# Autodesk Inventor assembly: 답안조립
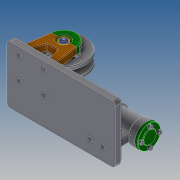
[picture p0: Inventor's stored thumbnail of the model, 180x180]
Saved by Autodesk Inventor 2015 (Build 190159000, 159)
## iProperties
Created: 2018-01
Part Number: 답안조립
Document SubType Name: Assembly
Designer: SCD-A03
Author: SCD-A03
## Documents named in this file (19)
- C:\Users\SCD-A03\Desktop\380108V1008\답안조립.iam
- C:\Users\SCD-A03\Desktop\380108V1008\플레이트.ipt
- C:\Users\SCD-A03\Desktop\380108V1008\3mm 와셔.ipt
- C:\Users\SCD-A03\Desktop\380108V1008\V-벨트풀리.ipt
- C:\Users\SCD-A03\Desktop\380108V1008\둥근머리볼트 M3x12.ipt
- C:\Users\SCD-A03\Desktop\380108V1008\베어링 8x22x7.ipt
- C:\Users\SCD-A03\Desktop\380108V1008\베어링커버-A.ipt
- C:\Users\SCD-A03\Desktop\380108V1008\볼트 M3x8.ipt
- C:\Users\SCD-A03\Desktop\380108V1008\볼트 M3x12.ipt
- C:\Users\SCD-A03\Desktop\380108V1008\스페이서.ipt
- C:\Users\SCD-A03\Desktop\380108V1008\지지대-A.ipt
- C:\Users\SCD-A03\Desktop\380108V1008\커넥팅로드-A.ipt
- C:\Users\SCD-A03\Desktop\380108V1008\커넥팅로드-B.ipt
- C:\Users\SCD-A03\Desktop\380108V1008\크랭크축.ipt
- C:\Users\SCD-A03\Desktop\380108V1008\플랜지.ipt
- C:\Users\SCD-A03\Desktop\380108V1008\피스톤.ipt
- C:\Users\SCD-A03\Desktop\380108V1008\하우징.ipt
- C:\Users\SCD-A03\Desktop\380108V1008\하우징커버-A.ipt
- C:\Users\SCD-A03\Desktop\380108V1008\하우징커버-B.ipt
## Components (9 placed, 8 different names)
1. 플레이트:1 — 각도:3
2. 3mm 와셔:1
3. V-벨트풀리:1 — 각도:3
4. 플랜지:1
5. 피스톤:1
6. 하우징:1
7. 하우징커버-A:1
8. 하우징커버-B:1
9. 3mm 와셔:2
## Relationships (1: Angle 1)
- 각도:3 [Angle]: 플레이트:1 ↔ V-벨트풀리:1
